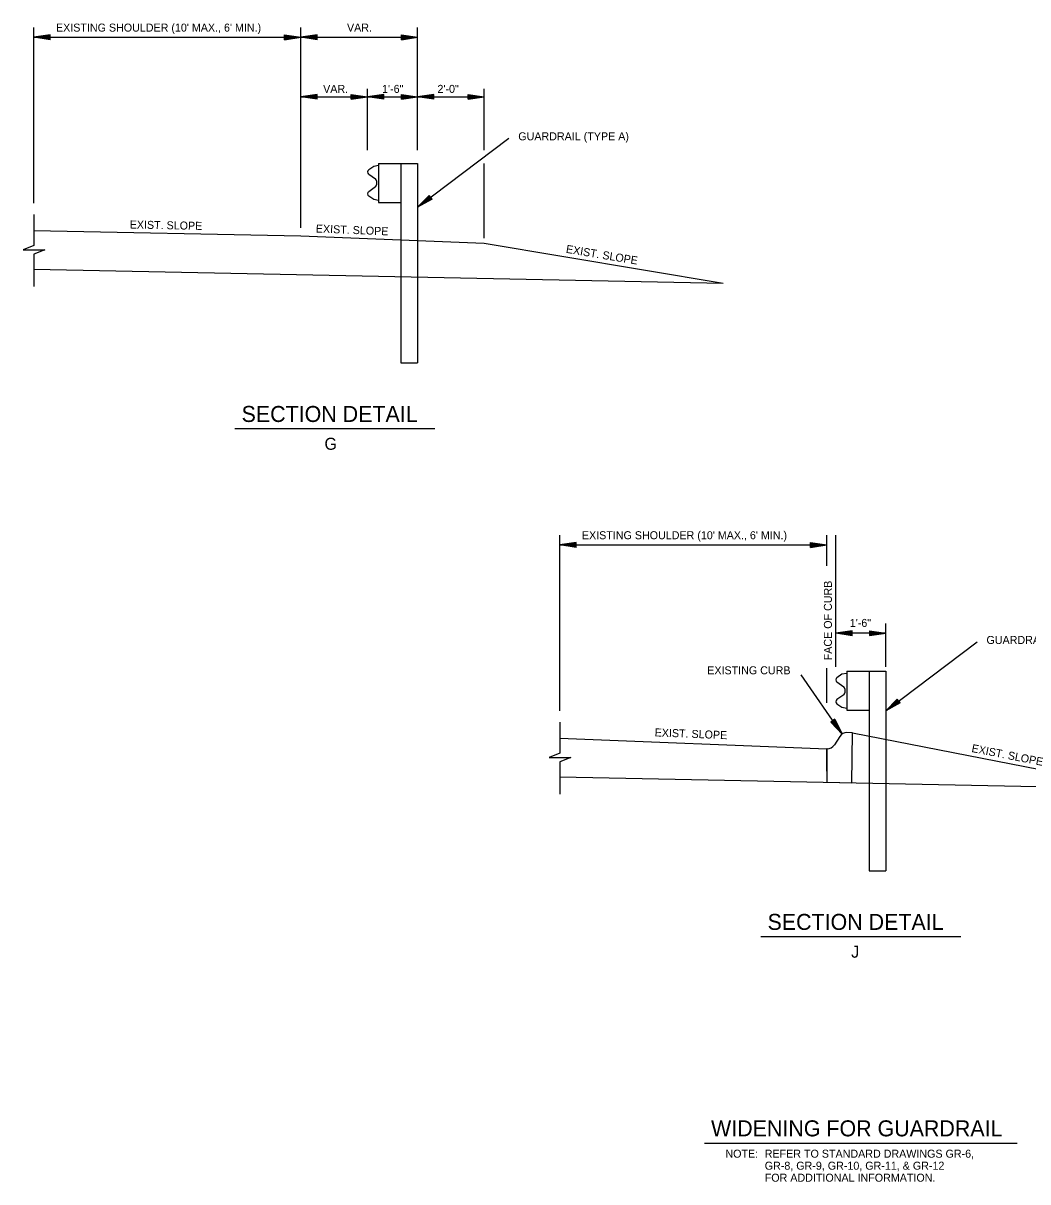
# Model space of a CAD drawing. Extents: x 1374136 to 1374281, y 380549 to 380948.
# Drawn here: x 1374140.5 to 1374215.8, y 380549.2 to 380636 of the extents above; entities that cross this region are included whole.
import ezdxf

# ---------------------------------------------------------------- set-up
doc = ezdxf.new("R2010")
doc.units = 0
for name, color, linetype in [('C-ANNO-TEXT', 7, 'Continuous'), ('Default', 7, 'Continuous'), ('R_Draft', 7, 'Continuous')]:
    doc.layers.add(name, color=color, linetype=linetype)

msp = doc.modelspace()

# ---------------------------------------------------------------- linework, layer by layer
at = {"layer": 'C-ANNO-TEXT'}
for points in [[(1374141.352, 380621.692), (1374141.352, 380619.362), (1374140.541, 380619.038), (1374142.164, 380619.038), (1374141.352, 380618.714), (1374141.352, 380616.29)], [(1374180.769, 380583.64), (1374180.769, 380581.31), (1374179.958, 380580.986), (1374181.58, 380580.986), (1374180.769, 380580.663), (1374180.769, 380578.238)]]:
    msp.add_lwpolyline(points, dxfattribs=at)
at = {"layer": 'Default'}
for p, q in [((1374141.352, 380622.537), (1374141.352, 380635.701)), ((1374161.352, 380620.688), (1374161.352, 380635.701)), ((1374170.102, 380626.526), (1374170.102, 380635.701)), ((1374142.57, 380635.159), (1374141.352, 380634.976)), ((1374141.352, 380634.976), (1374161.352, 380634.976)), ((1374142.57, 380634.793), (1374141.352, 380634.976)), ((1374142.57, 380635.128), (1374141.557, 380634.976)), ((1374142.57, 380634.824), (1374141.557, 380634.976)), ((1374142.57, 380635.096), (1374141.766, 380634.976)), ((1374142.57, 380634.856), (1374141.766, 380634.976)), ((1374142.57, 380635.067), (1374141.97, 380634.977)), ((1374142.57, 380634.885), (1374141.97, 380634.977)), ((1374142.57, 380635.036), (1374142.174, 380634.977)), ((1374142.57, 380634.916), (1374142.174, 380634.977)), ((1374142.57, 380635.004), (1374142.378, 380634.977)), ((1374142.57, 380634.948), (1374142.378, 380634.977)), ((1374142.57, 380634.793), (1374142.57, 380635.159)), ((1374160.135, 380635.159), (1374161.352, 380634.976)), ((1374160.135, 380634.793), (1374160.135, 380635.159)), ((1374160.135, 380635.128), (1374161.148, 380634.976)), ((1374160.135, 380635.096), (1374160.939, 380634.976)), ((1374160.135, 380635.067), (1374160.735, 380634.977)), ((1374160.135, 380635.036), (1374160.531, 380634.977)), ((1374160.135, 380635.004), (1374160.327, 380634.977)), ((1374160.135, 380634.916), (1374160.531, 380634.977)), ((1374160.135, 380634.885), (1374160.735, 380634.977)), ((1374160.135, 380634.948), (1374160.327, 380634.977)), ((1374160.135, 380634.793), (1374161.352, 380634.976)), ((1374160.135, 380634.856), (1374160.939, 380634.976)), ((1374160.135, 380634.824), (1374161.148, 380634.976)), ((1374162.57, 380635.159), (1374161.352, 380634.976)), ((1374161.352, 380634.976), (1374170.102, 380634.976)), ((1374162.57, 380634.793), (1374161.352, 380634.976)), ((1374162.57, 380635.128), (1374161.557, 380634.976)), ((1374162.57, 380634.824), (1374161.557, 380634.976)), ((1374162.57, 380635.096), (1374161.766, 380634.976)), ((1374162.57, 380634.856), (1374161.766, 380634.976)), ((1374162.57, 380635.067), (1374161.97, 380634.977)), ((1374162.57, 380634.885), (1374161.97, 380634.977)), ((1374162.57, 380635.036), (1374162.174, 380634.977)), ((1374162.57, 380634.916), (1374162.174, 380634.977)), ((1374162.57, 380635.004), (1374162.378, 380634.977)), ((1374162.57, 380634.948), (1374162.378, 380634.977)), ((1374162.57, 380634.793), (1374162.57, 380635.159)), ((1374168.885, 380635.159), (1374170.102, 380634.976)), ((1374168.885, 380634.793), (1374168.885, 380635.159)), ((1374168.885, 380635.128), (1374169.898, 380634.976)), ((1374168.885, 380635.096), (1374169.689, 380634.976)), ((1374168.885, 380635.067), (1374169.485, 380634.977)), ((1374168.885, 380635.036), (1374169.281, 380634.977)), ((1374168.885, 380635.004), (1374169.077, 380634.977)), ((1374168.885, 380634.916), (1374169.281, 380634.977)), ((1374168.885, 380634.885), (1374169.485, 380634.977)), ((1374168.885, 380634.948), (1374169.077, 380634.977)), ((1374168.885, 380634.793), (1374170.102, 380634.976)), ((1374168.885, 380634.856), (1374169.689, 380634.976)), ((1374168.885, 380634.824), (1374169.898, 380634.976)), ((1374166.352, 380626.526), (1374166.352, 380631.108)), ((1374175.102, 380626.526), (1374175.102, 380631.108)), ((1374162.57, 380630.699), (1374161.352, 380630.516)), ((1374161.352, 380630.516), (1374166.352, 380630.516)), ((1374162.57, 380630.332), (1374161.352, 380630.516)), ((1374162.57, 380630.667), (1374161.557, 380630.516)), ((1374162.57, 380630.364), (1374161.557, 380630.516)), ((1374162.57, 380630.636), (1374161.766, 380630.516)), ((1374162.57, 380630.395), (1374161.766, 380630.516)), ((1374162.57, 380630.607), (1374161.97, 380630.516)), ((1374162.57, 380630.424), (1374161.97, 380630.516)), ((1374162.57, 380630.575), (1374162.174, 380630.516)), ((1374162.57, 380630.456), (1374162.174, 380630.516)), ((1374162.57, 380630.544), (1374162.378, 380630.517)), ((1374162.57, 380630.488), (1374162.378, 380630.517)), ((1374162.57, 380630.332), (1374162.57, 380630.699)), ((1374165.135, 380630.699), (1374166.352, 380630.516)), ((1374165.135, 380630.332), (1374165.135, 380630.699)), ((1374165.135, 380630.667), (1374166.148, 380630.516)), ((1374165.135, 380630.636), (1374165.939, 380630.516)), ((1374165.135, 380630.607), (1374165.735, 380630.516)), ((1374165.135, 380630.575), (1374165.531, 380630.516)), ((1374165.135, 380630.544), (1374165.327, 380630.517)), ((1374165.135, 380630.488), (1374165.327, 380630.517)), ((1374165.135, 380630.332), (1374166.352, 380630.516)), ((1374165.135, 380630.456), (1374165.531, 380630.516)), ((1374165.135, 380630.395), (1374165.939, 380630.516)), ((1374165.135, 380630.364), (1374166.148, 380630.516)), ((1374165.135, 380630.424), (1374165.735, 380630.516)), ((1374167.57, 380630.699), (1374166.352, 380630.516)), ((1374166.352, 380630.516), (1374170.102, 380630.516)), ((1374167.57, 380630.332), (1374166.352, 380630.516)), ((1374167.57, 380630.667), (1374166.557, 380630.516)), ((1374167.57, 380630.364), (1374166.557, 380630.516)), ((1374167.57, 380630.636), (1374166.766, 380630.516)), ((1374167.57, 380630.395), (1374166.766, 380630.516)), ((1374167.57, 380630.607), (1374166.97, 380630.516)), ((1374167.57, 380630.424), (1374166.97, 380630.516)), ((1374167.57, 380630.575), (1374167.174, 380630.516)), ((1374167.57, 380630.456), (1374167.174, 380630.516)), ((1374167.57, 380630.544), (1374167.378, 380630.517)), ((1374167.57, 380630.488), (1374167.378, 380630.517)), ((1374167.57, 380630.332), (1374167.57, 380630.699)), ((1374168.885, 380630.699), (1374170.102, 380630.516)), ((1374168.885, 380630.332), (1374168.885, 380630.699)), ((1374168.885, 380630.667), (1374169.898, 380630.516)), ((1374168.885, 380630.636), (1374169.689, 380630.516)), ((1374168.885, 380630.607), (1374169.485, 380630.516)), ((1374168.885, 380630.575), (1374169.281, 380630.516)), ((1374168.885, 380630.544), (1374169.077, 380630.517)), ((1374168.885, 380630.488), (1374169.077, 380630.517)), ((1374168.885, 380630.332), (1374170.102, 380630.516)), ((1374168.885, 380630.456), (1374169.281, 380630.516)), ((1374168.885, 380630.395), (1374169.689, 380630.516)), ((1374168.885, 380630.364), (1374169.898, 380630.516)), ((1374168.885, 380630.424), (1374169.485, 380630.516)), ((1374171.32, 380630.699), (1374170.102, 380630.516)), ((1374170.102, 380630.516), (1374175.102, 380630.516)), ((1374171.32, 380630.332), (1374170.102, 380630.516)), ((1374171.32, 380630.667), (1374170.307, 380630.516)), ((1374171.32, 380630.364), (1374170.307, 380630.516)), ((1374171.32, 380630.636), (1374170.516, 380630.516)), ((1374171.32, 380630.395), (1374170.516, 380630.516)), ((1374171.32, 380630.607), (1374170.72, 380630.516)), ((1374171.32, 380630.424), (1374170.72, 380630.516)), ((1374171.32, 380630.575), (1374170.924, 380630.516)), ((1374171.32, 380630.456), (1374170.924, 380630.516)), ((1374171.32, 380630.544), (1374171.128, 380630.517)), ((1374171.32, 380630.488), (1374171.128, 380630.517)), ((1374171.32, 380630.332), (1374171.32, 380630.699)), ((1374173.885, 380630.699), (1374175.102, 380630.516)), ((1374173.885, 380630.332), (1374173.885, 380630.699)), ((1374173.885, 380630.667), (1374174.898, 380630.516)), ((1374173.885, 380630.636), (1374174.689, 380630.516)), ((1374173.885, 380630.607), (1374174.485, 380630.516)), ((1374173.885, 380630.575), (1374174.281, 380630.516)), ((1374173.885, 380630.544), (1374174.077, 380630.517)), ((1374173.885, 380630.488), (1374174.077, 380630.517)), ((1374173.885, 380630.332), (1374175.102, 380630.516)), ((1374173.885, 380630.456), (1374174.281, 380630.516)), ((1374173.885, 380630.395), (1374174.689, 380630.516)), ((1374173.885, 380630.364), (1374174.898, 380630.516)), ((1374173.885, 380630.424), (1374174.485, 380630.516)), ((1374170.102, 380622.247), (1374176.948, 380627.42)), ((1374166.814, 380625.297), (1374166.438, 380625.045)), ((1374167.177, 380625.368), (1374166.814, 380625.297)), ((1374167.177, 380625.526), (1374170.102, 380625.526)), ((1374167.177, 380625.526), (1374167.177, 380622.601)), ((1374168.852, 380625.526), (1374168.852, 380610.577)), ((1374170.102, 380625.526), (1374170.102, 380610.577)), ((1374175.102, 380619.914), (1374175.102, 380625.526)), ((1374166.435, 380624.725), (1374166.947, 380624.366)), ((1374167.029, 380624.207), (1374167.029, 380624.063)), ((1374166.947, 380623.76), (1374166.435, 380623.401)), ((1374167.029, 380624.063), (1374167.029, 380623.919)), ((1374166.438, 380623.081), (1374166.814, 380622.829)), ((1374166.814, 380622.829), (1374167.177, 380622.758)), ((1374167.177, 380622.601), (1374168.852, 380622.601)), ((1374170.965, 380623.125), (1374170.102, 380622.247)), ((1374171.182, 380622.836), (1374170.102, 380622.247)), ((1374170.985, 380623.102), (1374170.264, 380622.367)), ((1374171.167, 380622.859), (1374170.264, 380622.367)), ((1374171.006, 380623.074), (1374170.437, 380622.499)), ((1374171.144, 380622.884), (1374170.437, 380622.499)), ((1374171.019, 380623.049), (1374170.597, 380622.62)), ((1374171.126, 380622.91), (1374170.597, 380622.62)), ((1374171.038, 380623.029), (1374170.757, 380622.743)), ((1374171.106, 380622.936), (1374170.757, 380622.743)), ((1374171.056, 380623.003), (1374170.921, 380622.866)), ((1374171.093, 380622.963), (1374170.921, 380622.866)), ((1374171.182, 380622.836), (1374170.965, 380623.125)), ((1374141.352, 380620.488), (1374161.352, 380620.088)), ((1374161.352, 380620.088), (1374175.102, 380619.538)), ((1374175.102, 380619.538), (1374193, 380616.555)), ((1374141.352, 380617.588), (1374193, 380616.555)), ((1374156.41, 380605.64), (1374171.395, 380605.64)), ((1374180.769, 380584.486), (1374180.769, 380597.65)), ((1374200.769, 380595.36), (1374200.769, 380597.65)), ((1374201.444, 380587.787), (1374201.444, 380597.65)), ((1374181.986, 380597.108), (1374180.769, 380596.924)), ((1374180.769, 380596.924), (1374200.769, 380596.924)), ((1374181.986, 380596.741), (1374180.769, 380596.924)), ((1374181.986, 380597.076), (1374180.973, 380596.924)), ((1374181.986, 380596.772), (1374180.973, 380596.924)), ((1374181.986, 380597.044), (1374181.182, 380596.925)), ((1374181.986, 380596.804), (1374181.182, 380596.925)), ((1374181.986, 380597.015), (1374181.386, 380596.925)), ((1374181.986, 380596.833), (1374181.386, 380596.925)), ((1374181.986, 380596.984), (1374181.59, 380596.925)), ((1374181.986, 380596.865), (1374181.59, 380596.925)), ((1374181.986, 380596.952), (1374181.794, 380596.925)), ((1374181.986, 380596.896), (1374181.794, 380596.925)), ((1374181.986, 380596.741), (1374181.986, 380597.108)), ((1374199.551, 380596.741), (1374199.552, 380597.108)), ((1374199.551, 380596.952), (1374199.743, 380596.925)), ((1374199.551, 380596.865), (1374199.948, 380596.925)), ((1374199.551, 380596.804), (1374200.356, 380596.925)), ((1374199.551, 380596.833), (1374200.152, 380596.925)), ((1374199.551, 380596.896), (1374199.743, 380596.925)), ((1374199.551, 380596.741), (1374200.769, 380596.924)), ((1374199.551, 380596.772), (1374200.565, 380596.924)), ((1374199.552, 380597.108), (1374200.769, 380596.924)), ((1374199.552, 380597.076), (1374200.565, 380596.924)), ((1374199.552, 380597.044), (1374200.356, 380596.925)), ((1374199.552, 380597.015), (1374200.152, 380596.925)), ((1374199.552, 380596.984), (1374199.948, 380596.925)), ((1374202.661, 380590.487), (1374201.444, 380590.305)), ((1374202.661, 380590.12), (1374201.444, 380590.305)), ((1374205.194, 380590.305), (1374201.444, 380590.305)), ((1374202.661, 380590.456), (1374201.648, 380590.305)), ((1374202.661, 380590.152), (1374201.648, 380590.305)), ((1374202.661, 380590.424), (1374201.857, 380590.305)), ((1374202.661, 380590.184), (1374201.857, 380590.305)), ((1374202.661, 380590.395), (1374202.061, 380590.305)), ((1374202.661, 380590.213), (1374202.061, 380590.305)), ((1374202.661, 380590.363), (1374202.265, 380590.305)), ((1374202.661, 380590.244), (1374202.265, 380590.305)), ((1374202.661, 380590.332), (1374202.469, 380590.305)), ((1374202.661, 380590.276), (1374202.469, 380590.305)), ((1374202.661, 380590.12), (1374202.661, 380590.487)), ((1374203.976, 380590.49), (1374205.194, 380590.305)), ((1374203.976, 380590.49), (1374203.976, 380590.123)), ((1374203.976, 380590.458), (1374204.99, 380590.305)), ((1374203.976, 380590.427), (1374204.781, 380590.305)), ((1374203.976, 380590.397), (1374204.577, 380590.305)), ((1374203.976, 380590.366), (1374204.373, 380590.305)), ((1374203.976, 380590.334), (1374204.168, 380590.305)), ((1374203.976, 380590.123), (1374205.194, 380590.305)), ((1374203.976, 380590.247), (1374204.373, 380590.305)), ((1374203.976, 380590.186), (1374204.781, 380590.305)), ((1374203.976, 380590.154), (1374204.99, 380590.305)), ((1374203.976, 380590.215), (1374204.577, 380590.305)), ((1374203.976, 380590.278), (1374204.168, 380590.305)), ((1374205.194, 380587.787), (1374205.194, 380591.03)), ((1374205.194, 380584.494), (1374212.039, 380589.667)), ((1374200.769, 380585.083), (1374200.769, 380587.694)), ((1374201.915, 380582.749), (1374198.842, 380587.193)), ((1374201.905, 380587.224), (1374201.529, 380586.972)), ((1374202.269, 380587.294), (1374201.905, 380587.224)), ((1374202.269, 380587.452), (1374205.194, 380587.452)), ((1374202.269, 380587.452), (1374202.269, 380584.527)), ((1374203.944, 380587.452), (1374203.944, 380572.504)), ((1374205.194, 380587.452), (1374205.194, 380572.504)), ((1374201.526, 380586.651), (1374202.038, 380586.292)), ((1374202.121, 380586.133), (1374202.121, 380585.989)), ((1374202.121, 380585.989), (1374202.121, 380585.846)), ((1374202.038, 380585.686), (1374201.526, 380585.328)), ((1374201.529, 380585.007), (1374201.905, 380584.755)), ((1374206.056, 380585.372), (1374205.194, 380584.494)), ((1374206.274, 380585.084), (1374205.194, 380584.494)), ((1374206.077, 380585.349), (1374205.355, 380584.614)), ((1374206.258, 380585.106), (1374205.355, 380584.614)), ((1374206.097, 380585.321), (1374205.528, 380584.746)), ((1374206.236, 380585.132), (1374205.528, 380584.746)), ((1374206.11, 380585.296), (1374205.688, 380584.867)), ((1374206.218, 380585.157), (1374205.688, 380584.867)), ((1374206.13, 380585.276), (1374205.849, 380584.99)), ((1374206.197, 380585.183), (1374205.849, 380584.99)), ((1374206.148, 380585.25), (1374206.013, 380585.113)), ((1374206.184, 380585.21), (1374206.013, 380585.113)), ((1374206.274, 380585.084), (1374206.056, 380585.372)), ((1374201.905, 380584.755), (1374202.269, 380584.685)), ((1374202.269, 380584.527), (1374203.944, 380584.527)), ((1374201.371, 380583.853), (1374201.074, 380583.648)), ((1374201.074, 380583.648), (1374201.915, 380582.749)), ((1374201.097, 380583.667), (1374201.801, 380582.916)), ((1374201.127, 380583.687), (1374201.676, 380583.094)), ((1374201.152, 380583.699), (1374201.563, 380583.259)), ((1374201.173, 380583.717), (1374201.447, 380583.424)), ((1374201.2, 380583.734), (1374201.33, 380583.593)), ((1374201.241, 380583.769), (1374201.33, 380583.593)), ((1374201.269, 380583.781), (1374201.447, 380583.424)), ((1374201.296, 380583.8), (1374201.563, 380583.259)), ((1374201.322, 380583.817), (1374201.676, 380583.094)), ((1374201.348, 380583.839), (1374201.801, 380582.916)), ((1374201.371, 380583.853), (1374201.915, 380582.749)), ((1374180.769, 380582.436), (1374200.769, 380581.636)), ((1374202.694, 380582.848), (1374225.934, 380578.287)), ((1374200.769, 380579.961), (1374200.769, 380581.636)), ((1374180.769, 380579.536), (1374223.971, 380578.672)), ((1374195.827, 380567.566), (1374210.811, 380567.566)), ((1374191.594, 380552.092), (1374215.044, 380552.092))]:
    msp.add_line(p, q, dxfattribs=at)
for centre, start, end in [((1374166.547, 380624.884), 124.15804, 234.74711), ((1374166.834, 380624.207), 360, 54.74711), ((1374166.547, 380623.242), 125.25289, 235.84196), ((1374166.834, 380623.919), 305.25289, 0), ((1374201.639, 380586.81), 124.15804, 234.74711), ((1374201.926, 380586.133), 360, 54.74711), ((1374201.639, 380585.168), 125.25289, 235.84196), ((1374201.926, 380585.846), 305.25289, 0)]:
    msp.add_arc(centre, 0.195, start, end, dxfattribs=at)
at = {"layer": 'R_Draft'}
for p, q in [((1374168.852, 380610.577), (1374170.102, 380610.577)), ((1374201.736, 380582.564), (1374201.336, 380581.928)), ((1374202.694, 380582.848), (1374202.277, 380582.856)), ((1374202.644, 380579.099), (1374202.694, 380582.848)), ((1374200.794, 380581.636), (1374200.769, 380581.636)), ((1374200.769, 380581.636), (1374200.769, 380581.636)), ((1374200.769, 380579.136), (1374200.769, 380579.136)), ((1374200.769, 380579.136), (1374200.769, 380579.136)), ((1374200.769, 380579.136), (1374202.644, 380579.099)), ((1374203.944, 380572.504), (1374205.194, 380572.504))]:
    msp.add_line(p, q, dxfattribs=at)
msp.add_lwpolyline([(1374200.769, 380581.636), (1374200.769, 380579.136)], dxfattribs=at)
for centre, start, end in [((1374202.265, 380582.231), 88.85424, 147.85152), ((1374200.807, 380582.261), 268.85424, 327.85152)]:
    msp.add_arc(centre, 0.625, start, end, dxfattribs=at)

# ---------------------------------------------------------------- texts
at = {"layer": 'Default'}
for s, height, p in [("EXISTING SHOULDER (10' MAX., 6' MIN.)", 0.6, (1374143, 380635.401)), ('VAR.', 0.6, (1374164.811, 380635.401)), ('VAR.', 0.6, (1374163.023, 380630.808)), ('1\'-6"', 0.6, (1374167.439, 380630.808)), ('2\'-0"', 0.6, (1374171.591, 380630.808)), ('GUARDRAIL (TYPE A)', 0.6, (1374177.648, 380627.253)), ('SECTION DETAIL', 1.2, (1374156.91, 380606.14)), ('G', 0.9, (1374163.123, 380604.056)), ("EXISTING SHOULDER (10' MAX., 6' MIN.)", 0.6, (1374182.416, 380597.35)), ('1\'-6"', 0.6, (1374202.492, 380590.777)), ('GUARDRAIL (TYPE A)', 0.6, (1374212.739, 380589.5)), ('EXISTING CURB', 0.6, (1374191.81, 380587.227)), ('SECTION DETAIL', 1.2, (1374196.327, 380568.066)), ('J', 0.9, (1374202.596, 380565.983)), ('WIDENING FOR GUARDRAIL', 1.2, (1374192.094, 380552.592)), ('NOTE:', 0.6, (1374193.171, 380550.992)), ('REFER TO STANDARD DRAWINGS GR-6,', 0.6, (1374196.119, 380550.992)), ('GR-8, GR-9, GR-10, GR-11, & GR-12', 0.6, (1374196.119, 380550.092)), ('FOR ADDITIONAL INFORMATION.', 0.6, (1374196.119, 380549.192))]:
    msp.add_text(s, height=height, dxfattribs=at).set_placement(p)
for s, rotation, p in [('EXIST. SLOPE', 358.85424, (1374148.52, 380620.645)), ('EXIST. SLOPE', 357.70939, (1374162.467, 380620.344)), ('EXIST. SLOPE', 350.53768, (1374181.191, 380618.827)), ('FACE OF CURB', 90, (1374201.154, 380588.276)), ('EXIST. SLOPE', 357.70939, (1374187.86, 380582.577)), ('EXIST. SLOPE', 348.8964, (1374211.585, 380581.409))]:
    msp.add_text(s, height=0.6, rotation=rotation, dxfattribs=at).set_placement(p)

doc.saveas('drawing.dxf')
